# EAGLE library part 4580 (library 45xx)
4 x 4 MULTIPORT REGISTER
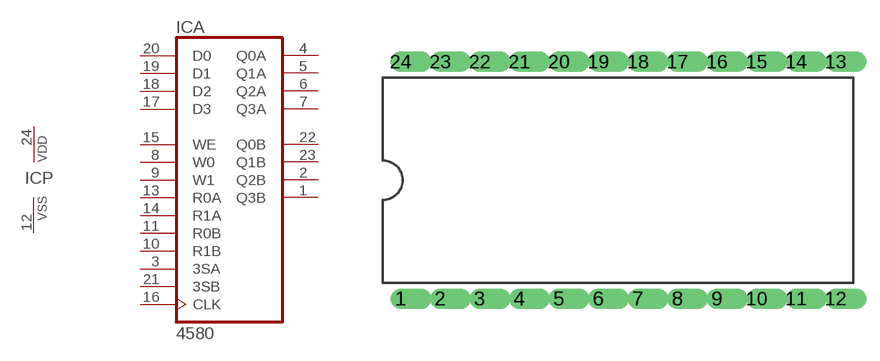
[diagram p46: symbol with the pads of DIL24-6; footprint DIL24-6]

Designator prefix IC; gates A=4580 P=PWRN

## 4580N  [DIL24-6]
1  A:Q3B  out
2  A:Q2B  out
3  A:3SA  in
4  A:Q0A  out
5  A:Q1A  out
6  A:Q2A  out
7  A:Q3A  out
8  A:W0  in
9  A:W1  in
10  A:R1B  in
11  A:R0B  in
12  P:VSS  pwr
13  A:R0A  in
14  A:R1A  in
15  A:WE  in
16  A:CLK  in
17  A:D3  in
18  A:D2  in
19  A:D1  in
20  A:D0  in
21  A:3SB  in
22  A:Q0B  out
23  A:Q1B  out
24  P:VDD  pwr

## Footprint DIL24-6 (pad centres in mm)
Dual In Line 0.6 inch
drill 0.813 offset: 1 -13.97,-7.62; 2 -11.43,-7.62; 3 -8.89,-7.62; 4 -6.35,-7.62; 5 -3.81,-7.62; 6 -1.27,-7.62; 7 1.27,-7.62; 8 3.81,-7.62; 9 6.35,-7.62; 10 8.89,-7.62; 11 11.43,-7.62; 12 13.97,-7.62; 13 13.97,7.62; 14 11.43,7.62; 15 8.89,7.62; 16 6.35,7.62; 17 3.81,7.62; 18 1.27,7.62; 19 -1.27,7.62; 20 -3.81,7.62; 21 -6.35,7.62; 22 -8.89,7.62; 23 -11.43,7.62; 24 -13.97,7.62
